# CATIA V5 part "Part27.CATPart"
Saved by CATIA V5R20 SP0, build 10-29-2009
Part number: 9TS2008M8
Revision: ANY
Definition: UNKNOWN
Nomenclature: 9TS2008M8
Source: Unknown
Bounding box of the stored display mesh (mm): x -10 to 10, y -10 to 10, z 0 to 8
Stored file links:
  C:\Users\Utente\Desktop\IO LAVORO\3D X SITO CF\CUMSA\3D files GR\GR 344038-15\Part27.CATPart
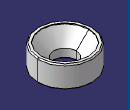
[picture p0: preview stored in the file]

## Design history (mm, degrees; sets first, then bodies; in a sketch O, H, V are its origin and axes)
Body1 "Chaflán1" (main body)
  Solid1: solid without history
